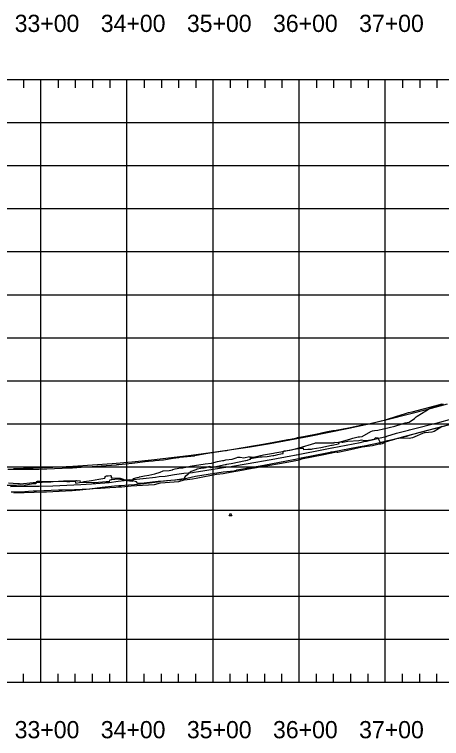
# Model space of a CAD drawing. Extents: x 704797 to 712284, y 374940 to 376945.
# Drawn here: x 710403 to 710899, y 375160 to 376001 of the extents above; entities that cross this region are included whole.
import ezdxf

# ---------------------------------------------------------------- set-up
doc = ezdxf.new("R2010")
doc.units = 0
for name, color, linetype in [('10', 7, 'Continuous'), ('12', 7, 'Continuous'), ('13', 7, 'Continuous'), ('48', 7, 'Continuous'), ('61', 7, 'Continuous'), ('Existing', 7, 'Continuous')]:
    doc.layers.add(name, color=color, linetype=linetype)

msp = doc.modelspace()

# ---------------------------------------------------------------- linework, layer by layer
msp.add_lwpolyline([(710654.02, 375421.79), (710655.52, 375418.79), (710652.52, 375418.79)], close=True)
at = {"layer": '10'}
for points in [[(710395.99, 375456.88), (710407.07, 375456.25), (710408.48, 375456.14), (710409.57, 375455.96), (710424.75, 375457.33), (710425, 375457.33), (710425.08, 375457.36), (710425.42, 375457.38), (710445.23, 375458.38), (710448.16, 375458.54), (710455.68, 375458.92), (710459.05, 375459), (710461.28, 375458.86), (710463.87, 375458.68), (710467.27, 375458.55), (710469.98, 375458.86), (710472.64, 375459.07), (710473.73, 375458.91), (710474.02, 375457.75), (710474.27, 375456.75), (710482.96, 375458.25), (710483.96, 375458.42), (710492.64, 375459.78), (710501.1, 375461.14), (710508.11, 375462.3), (710508.28, 375463.51), (710508.45, 375464.39), (710510, 375465.13), (710511.76, 375465.31), (710514.11, 375465.47), (710515.23, 375465.25), (710515.5, 375463.11), (710515.53, 375462.85), (710516.87, 375462.72), (710525.67, 375462.59), (710533.53, 375459.93), (710536.48, 375459.44), (710540.28, 375459.05), (710540.43, 375459.85), (710540.9, 375461.81), (710541.35, 375462.08), (710545.54, 375463.11), (710547.73, 375463.7), (710548.21, 375463.83), (710553.89, 375465.1), (710558.93, 375465.98), (710565.95, 375467.56), (710572.37, 375469.51), (710575.62, 375470.99), (710582.67, 375471.53), (710586.45, 375472.27), (710587.05, 375472.4), (710589.74, 375473.16), (710596.16, 375474.34), (710598.59, 375474.61), (710607.02, 375476.25), (710624.66, 375478.94), (710631.93, 375480.02), (710638.94, 375481.67), (710644.68, 375482.77), (710646.18, 375483.07), (710648.69, 375483.74), (710655.75, 375484.4), (710660.72, 375485.87), (710662.59, 375486.75), (710664.32, 375486.81), (710665.22, 375486.67), (710669.47, 375486.08), (710676.17, 375487.6), (710676.73, 375485.92), (710676.88, 375485.39), (710676.98, 375485.47), (710688.26, 375487.1), (710690.8, 375487.3), (710696.41, 375487.53), (710703.24, 375488.62), (710704.42, 375488.9), (710706.2, 375489.3), (710709.04, 375489.93), (710712.5, 375490.55), (710714.67, 375491.12), (710714.95, 375491.18), (710715.01, 375491.53), (710715.52, 375493.97), (710716.61, 375494.08), (710723.03, 375494.86), (710724.95, 375495.35), (710729.31, 375496.5), (710733.86, 375497.66), (710752.06, 375503.16), (710752.48, 375503.29), (710766.11, 375503.62), (710774.35, 375503.62), (710774.58, 375504.06), (710779.14, 375503.97), (710793.86, 375508), (710796.21, 375508.8), (710802.15, 375510.45), (710803.83, 375510.38), (710807.03, 375510.94), (710816.92, 375516.71), (710818.97, 375517.49), (710821.03, 375517.65), (710824.86, 375518.17), (710844.76, 375522.84), (710853.49, 375525.66), (710856.77, 375526.51), (710859.21, 375527.08), (710861.34, 375527.64), (710867.61, 375531.53), (710869.49, 375533.69), (710870.89, 375534.57), (710880.71, 375540.62), (710885.06, 375543.22), (710890.29, 375545.3), (710896.37, 375547.23), (710901.24, 375548.79)], [(710899.81, 375522.54), (710890.51, 375516.7), (710887.84, 375515.87), (710880, 375515.19), (710879.64, 375515.6), (710865.5, 375509.33), (710861.45, 375508.5), (710861.29, 375508.6), (710851.59, 375508.76), (710844.84, 375507.89), (710844.3, 375507.52), (710835.99, 375505.06), (710829.94, 375503.8), (710828.06, 375503.45), (710825.4, 375508.81), (710824.78, 375508.87), (710823.68, 375508.82), (710822.26, 375509.37), (710820.41, 375507.38), (710814.99, 375506.29), (710814.37, 375506.2), (710809.59, 375505.75), (710806.04, 375506.63), (710803.08, 375505.66), (710790.27, 375505.04), (710784.3, 375503.8), (710783.81, 375503.7), (710780.4, 375504.41), (710780.08, 375504.47), (710780.07, 375504.44), (710779.53, 375501.77), (710779.46, 375501.76), (710772, 375500.45), (710771.26, 375500.32), (710758.9, 375497.6), (710748.78, 375496), (710747.72, 375495.88), (710743.57, 375495.66), (710739.14, 375495.3), (710738.64, 375496.8), (710738.47, 375497.3), (710738.23, 375497.23), (710737.16, 375496.99), (710736.54, 375496.92), (710733.73, 375496.58), (710732.36, 375496.41), (710730.13, 375496), (710727.31, 375495.54), (710723.98, 375494.79), (710712.29, 375492.59), (710705.28, 375491.36), (710703.8, 375491.11), (710699.19, 375490.35), (710692.23, 375489.04), (710680.65, 375486.42), (710678.86, 375486.41), (710677.89, 375486.74), (710677.65, 375486.82), (710676.8, 375484.62), (710676.71, 375484.3), (710673.98, 375483.33), (710673.29, 375483.06), (710671.83, 375482.66), (710671.47, 375482.57), (710654.68, 375479.17), (710649.29, 375478.24), (710648.41, 375478.03), (710647.86, 375477.86), (710633.39, 375474.96), (710631.35, 375474.4), (710630.83, 375474.3), (710630.62, 375475.74), (710630.09, 375475.73), (710629.51, 375475.87), (710625.78, 375474.67), (710625.37, 375474.63), (710624.87, 375474.48), (710623.29, 375474.17), (710620.91, 375473.92), (710619.59, 375473.54), (710615.18, 375472.85), (710614.62, 375472.67), (710614.1, 375472.45), (710613.52, 375472.15), (710608.41, 375470.02), (710607.21, 375469.25), (710606.05, 375468.4), (710605.62, 375468.03), (710603.95, 375466.5), (710601.41, 375464.19), (710600.56, 375463.33), (710600.52, 375463.29), (710600.49, 375463.2), (710599.78, 375461.41), (710598.53, 375461.11), (710597.03, 375460.8), (710595.96, 375460.63), (710584.84, 375459.84), (710577.27, 375458.9), (710569.78, 375458.69), (710550.38, 375456.42), (710548.43, 375456.22), (710546.95, 375456.11), (710546.1, 375456.14), (710545.94, 375456.47), (710544.89, 375458.13), (710539.97, 375459.5), (710539.65, 375459.6), (710536.51, 375460.7), (710530.55, 375460.14), (710522.95, 375461.16), (710516.32, 375460.39), (710515.17, 375460.35), (710513.77, 375460.24), (710513.43, 375459.4), (710513.2, 375458.53), (710513.13, 375458.25), (710512.76, 375458.24), (710509.71, 375458.16), (710496.33, 375457.18), (710496.22, 375457.17), (710495.8, 375457.17), (710494.36, 375457.16), (710479.87, 375457.58), (710479.81, 375457.57), (710479.71, 375457.91), (710479.21, 375459.24), (710476.15, 375459.11), (710475.18, 375459.16), (710474.47, 375459.2), (710468.39, 375459.12), (710460.14, 375458.92), (710459.88, 375458.98), (710454.31, 375458.54), (710446, 375458.13), (710444.23, 375458.08), (710439.25, 375458.24), (710433.13, 375458.59), (710431.69, 375458.62), (710430.49, 375458.54), (710429.46, 375458.44), (710428.22, 375458.34), (710427.87, 375456.71), (710427.72, 375456.02), (710425.18, 375455.83), (710416.03, 375454.42), (710405.48, 375454.11), (710393.53, 375453.9)]]:
    msp.add_lwpolyline(points, dxfattribs=at)
at = {"layer": '12'}
for points in [[(710398.39, 375452.87), (710414.32, 375453.15), (710424.26, 375453.21), (710431.78, 375453.08), (710447.71, 375453.63), (710464.04, 375454.34), (710480.28, 375455), (710492.66, 375456.04), (710512.89, 375457.56), (710523.67, 375458.81), (710552.14, 375461.95), (710552.45, 375461.98), (710566.76, 375463.49), (710571.2, 375464.34), (710577.92, 375464.94), (710589.09, 375466.72), (710599.91, 375468.2), (710609.76, 375469.13), (710611.91, 375469.45), (710616.6, 375470.37), (710650.7, 375475.42), (710652.7, 375475.77), (710656.46, 375476.47), (710685.67, 375481.36), (710685.83, 375481.38), (710689.76, 375482.08), (710701.21, 375484.13), (710724.08, 375488.24), (710728.13, 375489.02), (710730.14, 375489.43), (710730.26, 375489.49), (710730.77, 375489.66), (710763.88, 375496.16), (710767.71, 375496.94), (710771.7, 375497.73), (710772.13, 375497.71), (710804.48, 375503.94), (710808.82, 375504.91), (710811.85, 375505.35), (710834.36, 375510.7), (710834.68, 375510.72), (710834.98, 375510.77), (710835.69, 375511.11), (710846.59, 375514.59), (710859.19, 375517.78), (710860.69, 375518.16), (710861.91, 375518.48), (710897.08, 375527.35), (710908.36, 375530.43)], [(710399.3, 375446.46), (710412.7, 375446.66), (710414.93, 375447.06), (710419.55, 375447.54), (710424.85, 375447.68), (710428.62, 375447.9), (710454.23, 375448.78), (710456.62, 375448.83), (710456.95, 375448.82), (710457.25, 375448.81), (710457.52, 375448.79), (710457.77, 375448.78), (710458, 375448.78), (710458.41, 375448.78), (710472.79, 375449.34), (710490.21, 375450), (710493.11, 375450.34), (710504.96, 375451.81), (710519.13, 375453.43), (710524.2, 375453.98), (710526.58, 375453.84), (710535.58, 375454.58), (710542.35, 375455.22), (710559.91, 375457.18), (710568.98, 375458.29), (710569.53, 375458.41), (710570.14, 375458.52), (710570.85, 375458.62), (710571.66, 375458.73), (710572.59, 375458.85), (710576.09, 375459.29), (710579.57, 375459.71), (710589.31, 375460.47), (710599.86, 375461.91), (710601.6, 375462.08), (710603.18, 375462.28), (710613.36, 375464.59), (710627.92, 375466.96), (710645.34, 375469.69), (710658.16, 375471.06), (710659.3, 375471.19), (710660.42, 375471.45), (710660.94, 375471.8), (710661.12, 375471.96), (710679.51, 375475.13), (710692.55, 375477.59), (710718.91, 375482.47), (710727.13, 375484.2), (710727.73, 375484.28), (710735.9, 375485.98), (710765.66, 375491.93), (710769.65, 375492.64), (710770.08, 375492.7), (710770.9, 375492.86), (710772.11, 375493.09), (710802.36, 375498.88), (710809.32, 375500), (710827.62, 375504), (710836.75, 375506), (710843.45, 375507.63), (710860.33, 375511.62), (710860.46, 375511.8), (710874.16, 375515.74), (710893.69, 375520.74), (710915.47, 375526.74)]]:
    msp.add_lwpolyline(points, dxfattribs=at)
at = {"layer": '13'}
msp.add_lwpolyline([(710913.53, 375525.73), (710892.38, 375520.16), (710875.62, 375515.81), (710856.57, 375511.01), (710845.34, 375507.82), (710833.51, 375504.05), (710829.91, 375502.33), (710828.36, 375502.04), (710826.76, 375501.96), (710818.77, 375500.06), (710806.94, 375498.35), (710789.86, 375494.53), (710778.69, 375492.38), (710778.22, 375492.4), (710777.1, 375492.44), (710762.37, 375489.54), (710748.54, 375486.76), (710736.28, 375484.38), (710734.3, 375483.72), (710733.84, 375483.52), (710726.07, 375481.93), (710710.78, 375479.06), (710697.34, 375476.67), (710681.77, 375473.95), (710681.17, 375473.88), (710669.08, 375471.88), (710653.66, 375469.02), (710645.59, 375467.64), (710637.88, 375466.51), (710614.24, 375461.95), (710609.74, 375461.28), (710603.63, 375460.36), (710599.6, 375459.97), (710593.44, 375458.36), (710578.12, 375457.17), (710572.43, 375456.48), (710565.29, 375454.85), (710538.67, 375453.13), (710527.76, 375451.96), (710523.85, 375451.82), (710520.64, 375451.67), (710513.74, 375451.08), (710503.08, 375450.3), (710494.32, 375450.11), (710482.34, 375448.97), (710479.11, 375448.63), (710478.8, 375448.65), (710469.92, 375447.83), (710469.84, 375447.82), (710440.42, 375446.32), (710438.61, 375446.21), (710437.63, 375446.16), (710437.37, 375446.18), (710414.5, 375445.57), (710410.29, 375445.46), (710407.23, 375445.28), (710402.16, 375445.16)], dxfattribs=at)
at = {"layer": '48'}
msp.add_lwpolyline([(710401.94, 375473.63), (710424.86, 375474.31), (710447.77, 375475.24), (710470.69, 375476.44), (710493.61, 375477.89), (710516.52, 375479.61), (710539.44, 375481.59), (710562.36, 375483.83), (710585.27, 375486.33), (710608.19, 375489.09), (710631.11, 375492.11), (710676.94, 375498.93), (710699.86, 375502.74), (710722.77, 375506.8), (710745.69, 375511.13), (710768.61, 375515.71), (710791.52, 375520.56), (710814.44, 375525.67), (710837.36, 375531.03), (710860.27, 375536.66), (710883.19, 375542.55), (710906.11, 375548.7)], dxfattribs=at)
at = {"layer": '61'}
for p, q in [((708133.69, 375925.47), (712133.69, 375925.47)), ((710413.69, 375925.47), (710413.69, 375915.47)), ((710433.69, 375225.47), (710433.69, 375925.47)), ((710453.69, 375925.47), (710453.69, 375915.47)), ((710473.69, 375925.47), (710473.69, 375915.47)), ((710493.69, 375925.47), (710493.69, 375915.47)), ((710513.69, 375925.47), (710513.69, 375915.47)), ((710533.69, 375225.47), (710533.69, 375925.47)), ((710553.69, 375925.47), (710553.69, 375915.47)), ((710573.69, 375925.47), (710573.69, 375915.47)), ((710593.69, 375925.47), (710593.69, 375915.47)), ((710613.69, 375925.47), (710613.69, 375915.47)), ((710633.69, 375225.47), (710633.69, 375925.47)), ((710653.69, 375925.47), (710653.69, 375915.47)), ((710673.69, 375925.47), (710673.69, 375915.47)), ((710693.69, 375925.47), (710693.69, 375915.47)), ((710713.69, 375925.47), (710713.69, 375915.47)), ((710733.69, 375225.47), (710733.69, 375925.47)), ((710753.69, 375925.47), (710753.69, 375915.47)), ((710773.69, 375925.47), (710773.69, 375915.47)), ((710793.69, 375925.47), (710793.69, 375915.47)), ((710813.69, 375925.47), (710813.69, 375915.47)), ((710833.69, 375225.47), (710833.69, 375925.47)), ((710853.69, 375925.47), (710853.69, 375915.47)), ((710873.69, 375925.47), (710873.69, 375915.47)), ((710893.69, 375925.47), (710893.69, 375915.47)), ((708133.69, 375875.47), (712133.69, 375875.47)), ((708133.69, 375825.47), (712133.69, 375825.47)), ((708133.69, 375775.47), (712133.69, 375775.47)), ((708133.69, 375725.47), (712133.69, 375725.47)), ((708133.69, 375675.47), (712133.69, 375675.47)), ((708133.69, 375625.47), (712133.69, 375625.47)), ((708133.69, 375575.47), (712133.69, 375575.47)), ((708133.69, 375525.47), (712133.69, 375525.47)), ((708133.69, 375475.47), (712133.69, 375475.47)), ((708133.69, 375425.47), (712133.69, 375425.47)), ((708133.69, 375375.47), (712133.69, 375375.47)), ((708133.69, 375325.47), (712133.69, 375325.47)), ((708133.69, 375275.47), (712133.69, 375275.47)), ((710413.69, 375225.47), (710413.69, 375235.47)), ((710453.69, 375225.47), (710453.69, 375235.47)), ((710473.69, 375225.47), (710473.69, 375235.47)), ((710493.69, 375225.47), (710493.69, 375235.47)), ((710513.69, 375225.47), (710513.69, 375235.47)), ((710553.69, 375225.47), (710553.69, 375235.47)), ((710573.69, 375225.47), (710573.69, 375235.47)), ((710593.69, 375225.47), (710593.69, 375235.47)), ((710613.69, 375225.47), (710613.69, 375235.47)), ((710653.69, 375225.47), (710653.69, 375235.47)), ((710673.69, 375225.47), (710673.69, 375235.47)), ((710693.69, 375225.47), (710693.69, 375235.47)), ((710713.69, 375225.47), (710713.69, 375235.47)), ((710753.69, 375225.47), (710753.69, 375235.47)), ((710773.69, 375225.47), (710773.69, 375235.47)), ((710793.69, 375225.47), (710793.69, 375235.47)), ((710813.69, 375225.47), (710813.69, 375235.47)), ((710853.69, 375225.47), (710853.69, 375235.47)), ((710873.69, 375225.47), (710873.69, 375235.47)), ((710893.69, 375225.47), (710893.69, 375235.47)), ((708133.69, 375225.47), (712133.69, 375225.47))]:
    msp.add_line(p, q, dxfattribs=at)
at = {"layer": 'Existing'}
msp.add_lwpolyline([(710395.27, 375472.86), (710404.92, 375472.97), (710405.53, 375472.97), (710413.33, 375473), (710431.4, 375473.08), (710436.93, 375473.1), (710438.69, 375473.14), (710440.5, 375473.23), (710449.47, 375473.64), (710467.54, 375474.46), (710470.35, 375474.59), (710470.56, 375474.6), (710485.6, 375475.41), (710488.7, 375475.57), (710493.28, 375475.99), (710495.58, 375476.03), (710498.53, 375476.24), (710503.67, 375476.65), (710521.74, 375478.1), (710522.51, 375478.16), (710524.09, 375478.23), (710539.81, 375479.98), (710557.87, 375481.99), (710558.87, 375482.1), (710564.3, 375482.48), (710566.48, 375482.99), (710575.94, 375483.87), (710576.08, 375483.89), (710587.51, 375485.74), (710593.73, 375486.26), (710594.01, 375486.33), (710595.23, 375486.66), (710607.76, 375487.89), (710612.07, 375488.56), (710612.65, 375488.65), (710622.96, 375490.71), (710630.14, 375491.79), (710648.21, 375494.52), (710649.36, 375494.69), (710652.95, 375495.32), (710659.58, 375496.57), (710666.28, 375497.71), (710684.34, 375500.76), (710684.69, 375500.82), (710684.94, 375500.85), (710691.35, 375501.99), (710702.41, 375503.99), (710720.48, 375507.24), (710721.49, 375507.43), (710727.73, 375508.61), (710730.84, 375509.26), (710731.02, 375509.34), (710731.8, 375509.6), (710738.55, 375510.93), (710756.61, 375514.47), (710761.03, 375515.34), (710766.73, 375516.5), (710772.68, 375517.67), (710773.31, 375517.65), (710774.68, 375517.91), (710792.75, 375521.38), (710801.71, 375523.1), (710808.46, 375524.61), (710810.82, 375524.95), (710813.2, 375525.29), (710828.88, 375529), (710832.81, 375529.93), (710833.38, 375529.96), (710833.94, 375530.06), (710835.24, 375530.68), (710846.95, 375534.41), (710855.89, 375537.25), (710860.81, 375538.5), (710865.02, 375539.6), (710891.16, 375546.43), (710899.8, 375548.64)], dxfattribs=at)

# ---------------------------------------------------------------- texts
at = {"layer": '61'}
for s, p in [('33+00', (710403.32, 375980.47)), ('34+00', (710503.32, 375980.47)), ('35+00', (710603.32, 375980.47)), ('36+00', (710703.32, 375980.47)), ('37+00', (710803.32, 375980.47)), ('33+00', (710403.32, 375160.47)), ('34+00', (710503.32, 375160.47)), ('35+00', (710603.32, 375160.47)), ('36+00', (710703.32, 375160.47)), ('37+00', (710803.32, 375160.47))]:
    msp.add_text(s, height=20, dxfattribs=at).set_placement(p)

doc.saveas('drawing.dxf')
